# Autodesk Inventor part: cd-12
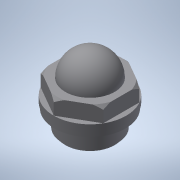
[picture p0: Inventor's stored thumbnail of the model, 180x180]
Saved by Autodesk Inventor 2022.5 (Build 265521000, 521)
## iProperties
Created: 2016-12
Part Number: cd-12
Material: 一般
Document SubType Name: Modeling
Designer: imaocorp
Density: 1 g/cm^3
Appearance: 既定
Author: imaocorp
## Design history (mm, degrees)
node "cd-12.x_t1"
node "cd-12"
node "Base1"
